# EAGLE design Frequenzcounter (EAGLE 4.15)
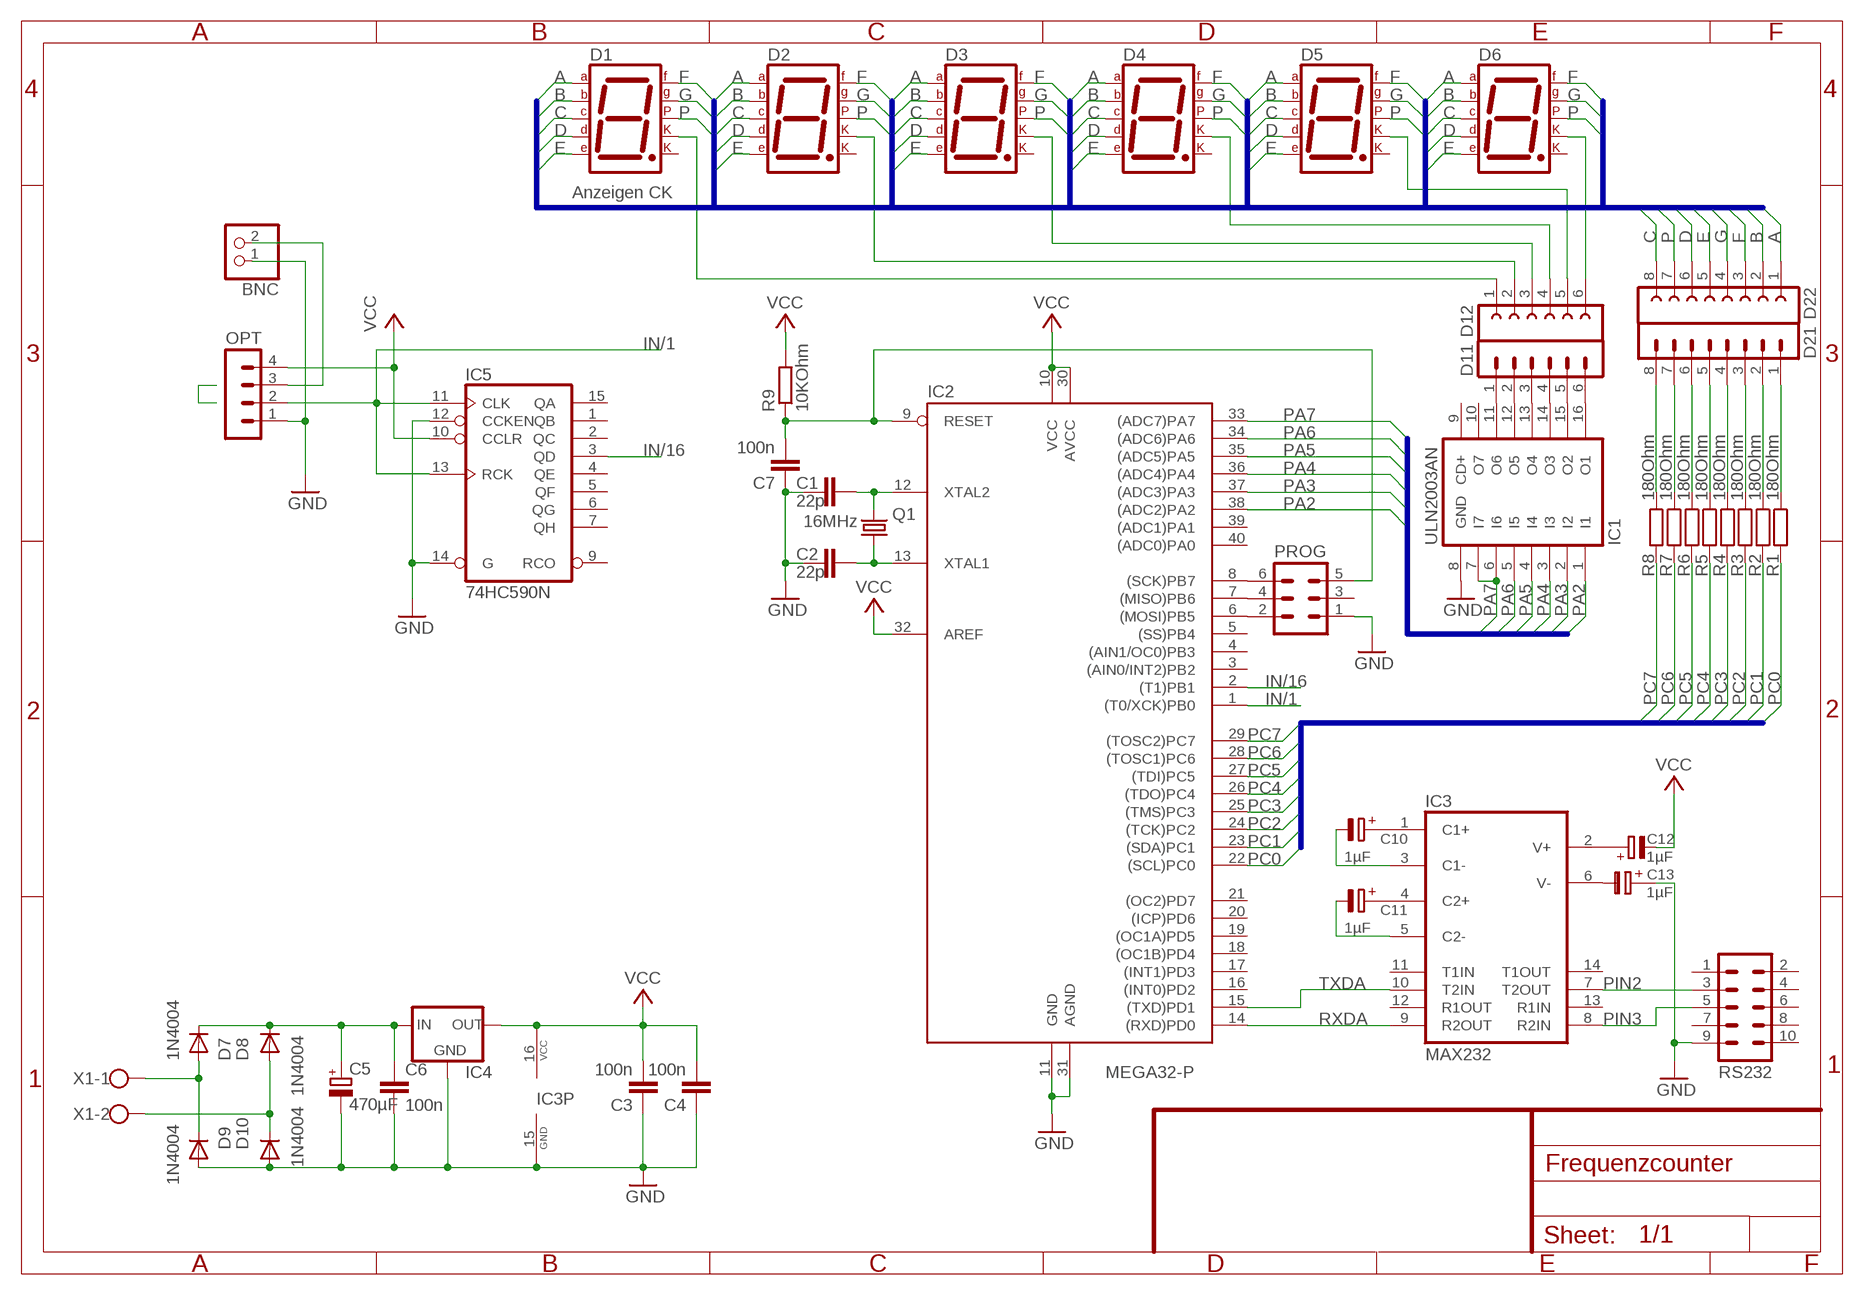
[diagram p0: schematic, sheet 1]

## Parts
BNC  PINHD-1X2  [1X02]
C1  22p  C-EU025-024X044  [C025-024X044]
C2  22p  C-EU025-024X044  [C025-024X044]
C3  100n  C-EU025-024X044  [C025-024X044]
C4  100n  C-EU025-024X044  [C025-024X044]
C5  470µF  CPOL-EUE5-8.5  [E5-8,5]
C6  100n  C-EU025-024X044  [C025-024X044]
C7  100n  C-EU025-024X044  [C025-024X044]
C10  1µF  E2,5-5  [E2,5-5]
C11  1µF  E2,5-5  [E2,5-5]
C12  1µF  E2,5-5  [E2,5-5]
C13  1µF  E2,5-5  [E2,5-5]
D1  7SEG-CK  [7SEG-13]
D2  7SEG-CK  [7SEG-13]
D3  7SEG-CK  [7SEG-13]
D4  7SEG-CK  [7SEG-13]
D5  7SEG-CK  [7SEG-13]
D6  7SEG-CK  [7SEG-13]
D7  1N4004  [DO41-10]
D8  1N4004  [DO41-10]
D9  1N4004  [DO41-10]
D10  1N4004  [DO41-10]
D11  MA06-1  [MA06-1]
D12  FE06-1  [FE06]
D21  MA08-1  [MA08-1]
D22  FE08-1  [FE08]
IC1  ULN2003AN  [DIL16]
IC2  MEGA32-P  [DIL40]
IC3  MAX232  [DIL16]
IC4  78XXS  [78XXS]
IC5  74HC590N  [DIL16]
OPT  MA04-1  [MA04-1]
PROG  ML6  [ML6]
Q1  16MHz  CRYTALHC49S  [HC49/S]
R1  180Ohm  R-EU_0207/10  [0207/10]
R2  180Ohm  R-EU_0207/10  [0207/10]
R3  180Ohm  R-EU_0207/10  [0207/10]
R4  180Ohm  R-EU_0207/10  [0207/10]
R5  180Ohm  R-EU_0207/10  [0207/10]
R6  180Ohm  R-EU_0207/10  [0207/10]
R7  180Ohm  R-EU_0207/10  [0207/10]
R8  180Ohm  R-EU_0207/10  [0207/10]
R9  10KOhm  R-EU_0207/10  [0207/10]
RS232  ML10  [ML10]
X1  W237-102  [W237-102]

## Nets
A: D1.7(A) D2.7(A) D3.7(A) D4.7(A) D5.7(A) D6.7(A) D22.1
B: D1.6(B) D2.6(B) D3.6(B) D4.6(B) D5.6(B) D6.6(B) D22.2
C: D1.4(C) D2.4(C) D3.4(C) D4.4(C) D5.4(C) D6.4(C) D22.8
D: D1.2(D) D2.2(D) D3.2(D) D4.2(D) D5.2(D) D6.2(D) D22.6
E: D1.1(E) D2.1(E) D3.1(E) D4.1(E) D5.1(E) D6.1(E) D22.5
F: D1.9(F) D2.9(F) D3.9(F) D4.9(F) D5.9(F) D6.9(F) D22.3
G: D1.10(G) D2.10(G) D3.10(G) D4.10(G) D5.10(G) D6.10(G) D22.4
GND: BNC.1 C1.1 C2.1 C3.1 C4.1 C5.- C6.2 C7.1 C13.+ D9.A D10.A IC1.8(GND) IC2.11(GND) IC2.31(AGND) IC3.15(GND) IC4.GND IC5.12(CCKEN) IC5.14(G) OPT.1 PROG.1 RS232.9
IN/1: IC2.1((T0/XCK)PB0) IC5.11(CLK) IC5.13(RCK) OPT.2
IN/16: IC2.2((T1)PB1) IC5.3(QD)
N$1: D21.8 R8.1
N$2: D2.3(CK1) D12.2
N$3: D3.3(CK1) D12.3
N$4: D4.3(CK1) D12.4
N$5: D5.3(CK1) D12.5
N$6: D6.3(CK1) D12.6
N$7: D21.7 R7.1
N$8: D21.6 R6.1
N$9: D21.5 R5.1
N$10: D21.4 R4.1
N$11: D21.3 R3.1
N$12: D21.2 R2.1
N$13: D21.1 R1.1
N$14: D11.6 IC1.16(O1)
N$15: D11.5 IC1.15(O2)
N$16: D11.4 IC1.14(O3)
N$17: D11.3 IC1.13(O4)
N$18: D11.2 IC1.12(O5)
N$19: D11.1 IC1.11(O6)
N$20: C10.+ IC3.1(C1+)
N$21: C11.+ IC3.4(C2+)
N$22: C11.- IC3.5(C2-)
N$23: C12.+ IC3.2(V+)
N$24: C13.- IC3.6(V-)
N$27: C1.2 IC2.12(XTAL2) Q1.2
N$28: C2.2 IC2.13(XTAL1) Q1.1
N$30: C10.- IC3.3(C1-)
N$35: IC2.6((MOSI)PB5) PROG.2
N$36: IC2.7((MISO)PB6) PROG.4
N$37: IC2.8((SCK)PB7) PROG.6
N$42: D7.A D9.C X1.1
N$43: D8.A D10.C X1.2
N$44: BNC.2 OPT.3
N$45: C5.+ C6.1 D7.C D8.C IC4.IN
P: D1.5(DP) D2.5(DP) D3.5(DP) D4.5(DP) D5.5(DP) D6.5(DP) D22.7
PA2: IC1.1(I1) IC2.38((ADC2)PA2)
PA3: IC1.2(I2) IC2.37((ADC3)PA3)
PA4: IC1.3(I3) IC2.36((ADC4)PA4)
PA5: IC1.4(I4) IC2.35((ADC5)PA5)
PA6: IC1.5(I5) IC2.34((ADC6)PA6)
PA7: IC1.6(I6) IC1.7(I7) IC2.33((ADC7)PA7)
PC0: IC2.22((SCL)PC0) R1.2
PC1: IC2.23((SDA)PC1) R2.2
PC2: IC2.24((TCK)PC2) R3.2
PC3: IC2.25((TMS)PC3) R4.2
PC4: IC2.26((TDO)PC4) R5.2
PC5: IC2.27((TDI)PC5) R6.2
PC6: IC2.28((TOSC1)PC6) R7.2
PC7: IC2.29((TOSC2)PC7) R8.2
PIN2: IC3.7(T2OUT) RS232.3
PIN3: IC3.8(R2IN) RS232.5
RESET: C7.2 IC2.9(RESET) PROG.5 R9.1
RXDA: IC2.14((RXD)PD0) IC3.9(R2OUT)
SEG1: D1.3(CK1) D12.1
TXDA: IC2.15((TXD)PD1) IC3.10(T2IN)
VCC: C3.2 C4.2 C12.- IC2.10(VCC) IC2.30(AVCC) IC2.32(AREF) IC3.16(VCC) IC4.OUT IC5.10(CCLR) OPT.4 R9.2
Unconnected: D1.8(CK2) D2.8(CK2) D3.8(CK2) D4.8(CK2) D5.8(CK2) D6.8(CK2) IC1.9(CD+) IC1.10(O7) IC2.3((AIN0/INT2)PB2) IC2.4((AIN1/OC0)PB3) IC2.5((SS)PB4) IC2.16((INT0)PD2) IC2.17((INT1)PD3) IC2.18((OC1B)PD4) IC2.19((OC1A)PD5) IC2.20((ICP)PD6) IC2.21((OC2)PD7) IC2.39((ADC1)PA1) IC2.40((ADC0)PA0) IC3.11(T1IN) IC3.12(R1OUT) IC3.13(R1IN) IC3.14(T1OUT) IC5.1(QB) IC5.2(QC) IC5.4(QE) IC5.5(QF) IC5.6(QG) IC5.7(QH) IC5.9(RCO) IC5.15(QA) PROG.3 RS232.1 RS232.2 RS232.4 RS232.6 RS232.7 RS232.8 RS232.10

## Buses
A,B,C,D,E,F,G,P
PC[0..7]
PA[2..7]

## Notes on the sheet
- Anzeigen CK

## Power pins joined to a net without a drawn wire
GND: IC5.8(GND)
VCC: IC5.16(VCC)

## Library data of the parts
BNC = pinhead:PINHD-1X2: PIN HEADER
C1-C4 C6 C7 = rcl:C-EU: CAPACITOR, European symbol
C5 = rcl:CPOL-EU: POLARIZED CAPACITOR, European symbol
C10-C13 = POLCAP:E2,5-5
D1-D6 = special:7SEG-CK: 7-segment DISPLAY single cathode, 13 mm
D7-D10 = diode:1N4004: DIODE
D11 = con-lstb:MA06-1: PIN HEADER
D12 = con-lsta:FE06-1: FEMALE HEADER
D21 = con-lstb:MA08-1: PIN HEADER
D22 = con-lsta:FE08-1: FEMALE HEADER
IC1 = uln-udn:ULN2003A: DRIVER ARRAY
IC2 = atmel:MEGA32-P: MICROCONTROLLER 32 Kbytes FLASH 2 Kbytes SRAM 1 Kbytes EEPROM USART 8-channel 10 bit ADC
IC3 = MAXIM:MAX232
IC4 = v-reg:78XXS: VOLTAGE REGULATOR
IC5 = 74xx-eu:74*590: 8-bit binary COUNTER, output register
OPT = con-lstb:MA04-1: PIN HEADER
PROG = con-harting-ml:ML6: HARTING
Q1 = crystal:CRYTAL: CRYSTAL
R1-R9 = rcl:R-EU_: RESISTOR, European symbol
RS232 = con-harting-ml:ML10: HARTING
X1 = con-wago-500:W237-102: WAGO SCREW CLAMP

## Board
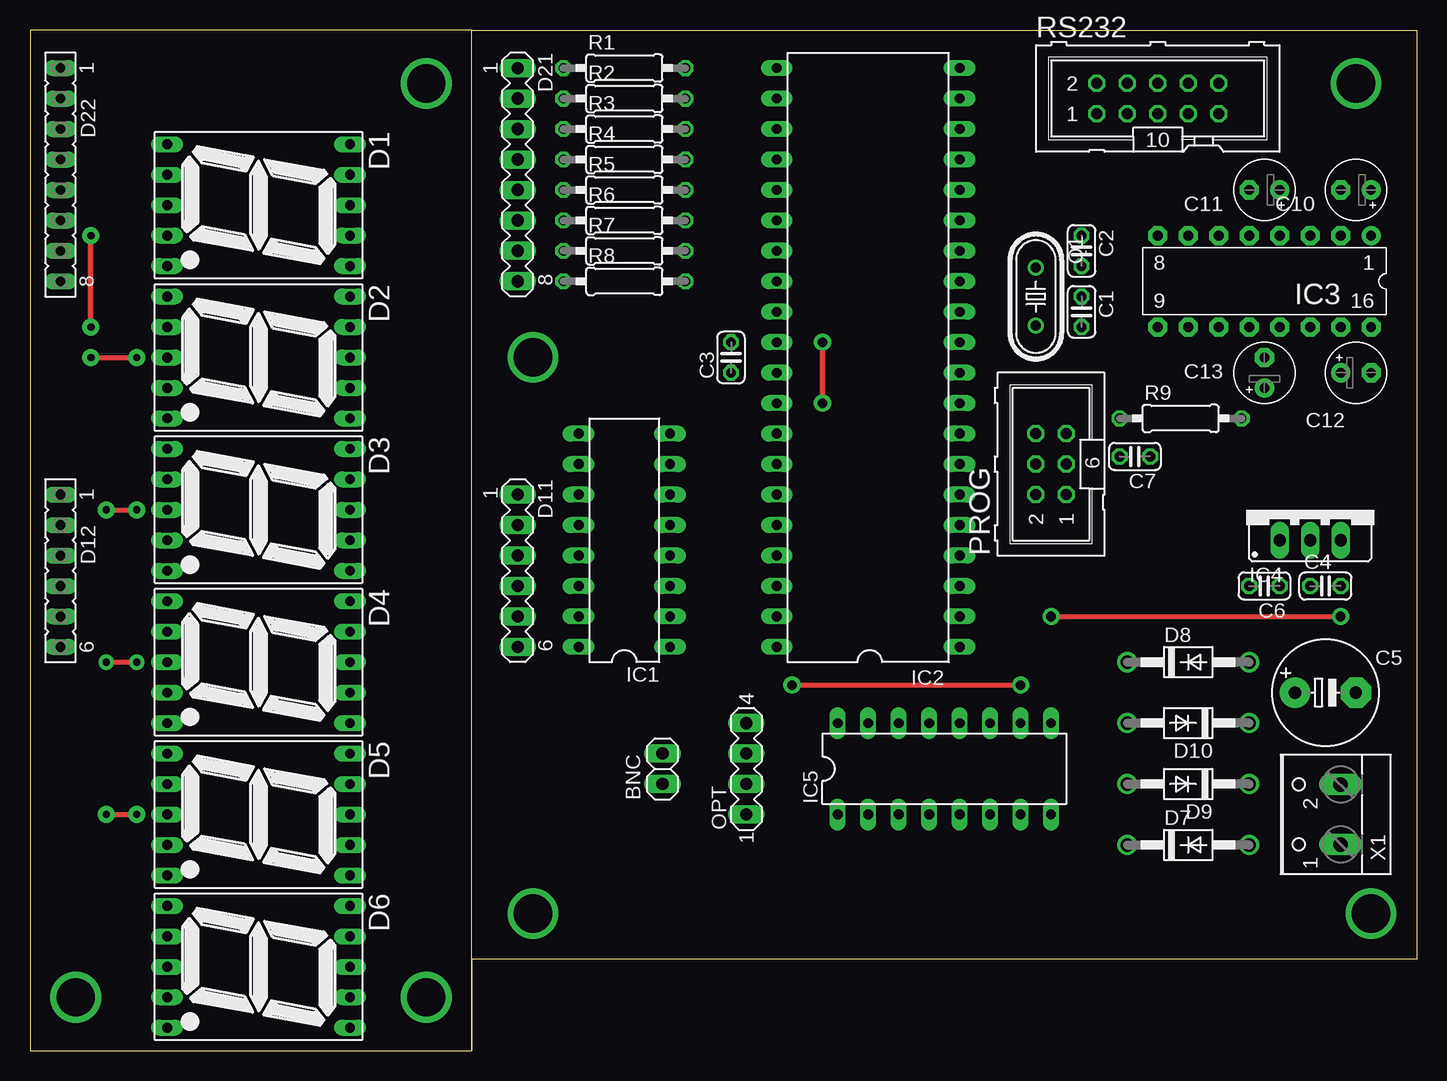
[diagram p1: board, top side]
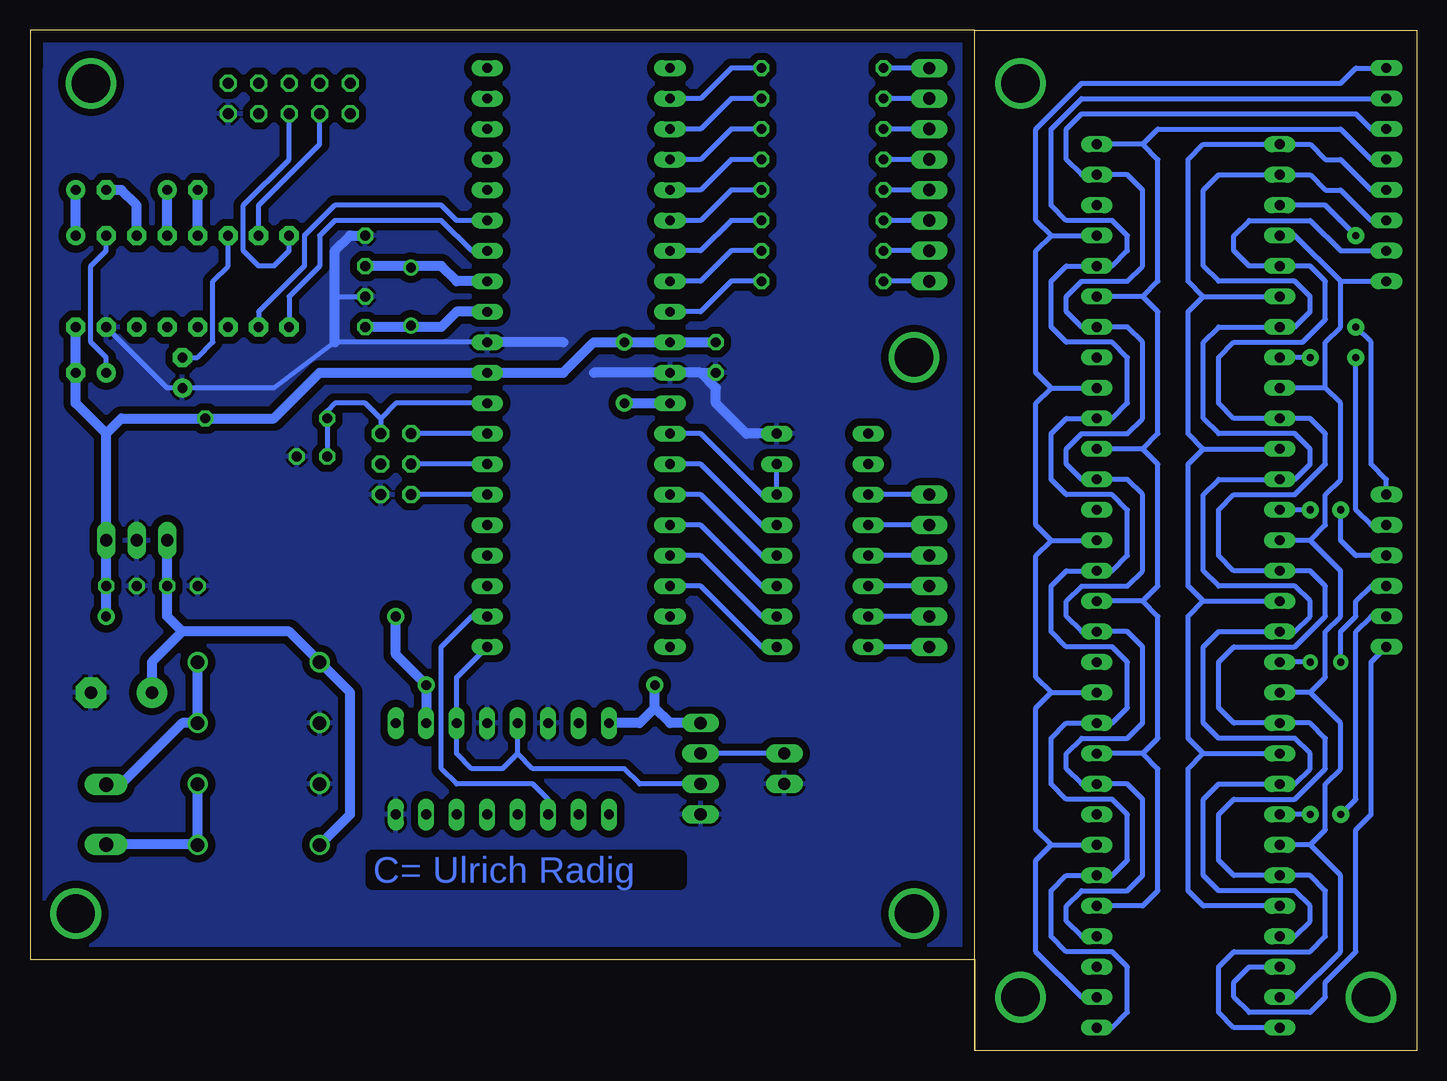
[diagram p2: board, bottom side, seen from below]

Size 115.57 x 85.09 mm. Coordinates in mm from the lower left corner, seen from the top.
Outline: 36.83,0 36.83,85.09
Outline: 36.83,85.09 0,85.09 0,0 36.83,0
Outline: 36.83,85.09 115.57,85.09 115.57,7.62 36.83,7.62 36.83,0
Copper layers (1*16): Top 0.035mm / dielectric 1.5mm / Bottom 0.035mm
Design rules "default": minimum track width 10mil, minimum drill 24mil, track to track 8mil, track to pad 8mil, pad to pad 8mil, via to via 8mil, smd to smd 8mil, copper to edge 40mil, drill to drill 8mil, minimum pad ring 10mil, minimum via ring 8mil, stop-mask expansion 4mil, vias tented up to drill 0mil, thermal gap 10mil

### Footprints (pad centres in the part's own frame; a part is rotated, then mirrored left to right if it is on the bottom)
1X02 = drill 1.016 long: 1 -1.27,0; 2 1.27,0
C025-024X044 = drill 0.813 octagon: 1 -1.27,0; 2 1.27,0
E5-8,5 = drill 1.016 pad 2.54 round: + -2.54,0 | drill 1.016 pad 2.54 octagon: - 2.54,0
E2,5-5 = drill 0.813 pad 1.6 round: + -1.27,0 | drill 0.813 pad 1.6 octagon: - 1.27,0
7SEG-13 = drill 0.813 long: 1 -5.08,-7.62; 2 -2.54,-7.62; 3 0,-7.62; 4 2.54,-7.62; 5 5.08,-7.62; 6 5.08,7.62; 7 2.54,7.62; 8 0,7.62; 9 -2.54,7.62; 10 -5.08,7.62
DO41-10 = drill 1.118 round: A 5.08,0; C -5.08,0
MA06-1 = drill 1.016 long: 1 -6.35,0; 2 -3.81,0; 3 -1.27,0; 4 1.27,0; 5 3.81,0; 6 6.35,0
FE06 = drill 0.813 long: 1 -6.35,0; 2 -3.81,0; 3 -1.27,0; 4 1.27,0; 5 3.81,0; 6 6.35,0
MA08-1 = drill 1.016 long: 1 -8.89,0; 2 -6.35,0; 3 -3.81,0; 4 -1.27,0; 5 1.27,0; 6 3.81,0; 7 6.35,0; 8 8.89,0
FE08 = drill 0.813 long: 1 -8.89,0; 2 -6.35,0; 3 -3.81,0; 4 -1.27,0; 5 1.27,0; 6 3.81,0; 7 6.35,0; 8 8.89,0
DIL16 = drill 0.813 long: 1 -8.89,-3.81; 2 -6.35,-3.81; 3 -3.81,-3.81; 4 -1.27,-3.81; 5 1.27,-3.81; 6 3.81,-3.81; 7 6.35,-3.81; 8 8.89,-3.81; 9 8.89,3.81; 10 6.35,3.81; 11 3.81,3.81; 12 1.27,3.81; 13 -1.27,3.81; 14 -3.81,3.81; 15 -6.35,3.81; 16 -8.89,3.81
DIL40 = drill 0.813 long: 1 -24.13,-7.62; 2 -21.59,-7.62; 3 -19.05,-7.62; 4 -16.51,-7.62; 5 -13.97,-7.62; 6 -11.43,-7.62; 7 -8.89,-7.62; 8 -6.35,-7.62; 9 -3.81,-7.62; 10 -1.27,-7.62; 11 1.27,-7.62; 12 3.81,-7.62; 13 6.35,-7.62; 14 8.89,-7.62; 15 11.43,-7.62; 16 13.97,-7.62; 17 16.51,-7.62; 18 19.05,-7.62; 19 21.59,-7.62; 20 24.13,-7.62; 21 24.13,7.62; 22 21.59,7.62; 23 19.05,7.62; 24 16.51,7.62; 25 13.97,7.62; 26 11.43,7.62; 27 8.89,7.62; 28 6.35,7.62; 29 3.81,7.62; 30 1.27,7.62; 31 -1.27,7.62; 32 -3.81,7.62; 33 -6.35,7.62; 34 -8.89,7.62; 35 -11.43,7.62; 36 -13.97,7.62; 37 -16.51,7.62; 38 -19.05,7.62; 39 -21.59,7.62; 40 -24.13,7.62
DIL16' = drill 0.813 pad 1.6 round: 1 -8.89,-3.81 | drill 0.813 pad 1.6 octagon: 2 -6.35,-3.81; 3 -3.81,-3.81; 4 -1.27,-3.81; 5 1.27,-3.81; 6 3.81,-3.81; 7 6.35,-3.81; 8 8.89,-3.81; 9 8.89,3.81; 10 6.35,3.81; 11 3.81,3.81; 12 1.27,3.81; 13 -1.27,3.81; 14 -3.81,3.81; 15 -6.35,3.81; 16 -8.89,3.81
78XXS = drill 1.016 long: GND 0,-2.54; IN -2.54,-2.54; OUT 2.54,-2.54
MA04-1 = drill 1.016 long: 1 -3.81,0; 2 -1.27,0; 3 1.27,0; 4 3.81,0
ML6 = drill 0.914 octagon: 1 -2.54,-1.27; 2 -2.54,1.27; 3 0,-1.27; 4 0,1.27; 5 2.54,-1.27; 6 2.54,1.27
HC49/S = drill 0.813 round: 1 -2.413,0; 2 2.413,0
0207/10 = drill 0.813 octagon: 1 -5.08,0; 2 5.08,0
ML10 = drill 0.914 octagon: 1 -5.08,-1.27; 2 -5.08,1.27; 3 -2.54,-1.27; 4 -2.54,1.27; 5 0,-1.27; 6 0,1.27; 7 2.54,-1.27; 8 2.54,1.27; 9 5.08,-1.27; 10 5.08,1.27
W237-102 = drill 1.194 long: 1 -2.5,-1.27; 2 2.5,-1.27

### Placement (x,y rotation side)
BNC  52.7,23.5 90 top
C1  87.63,61.59 270 top
C2  87.63,66.67 270 top
C3  58.42,57.78 90 top
C4  107.95,38.73 0 top
C5  107.95,29.85 0 top
C6  102.87,38.73 180 top
C7  92.08,49.53 180 top
C10  110.49,71.75 180 top
C11  102.87,71.75 180 top
C12  110.49,56.52 0 top
C13  102.87,56.52 90 top
D1  19.05,70.48 270 top
D2  19.05,57.78 270 top
D3  19.05,45.08 270 top
D4  19.05,32.39 270 top
D5  19.05,19.68 270 top
D6  19.05,6.98 270 top
D7  96.52,17.14 0 top
D8  96.52,32.39 0 top
D9  96.52,22.22 180 top
D10  96.52,27.3 180 top
D11  40.64,40 270 top
D12  2.54,40 270 top
D21  40.64,73.02 270 top
D22  2.54,73.02 270 top
IC1  49.53,42.55 90 top
IC2  69.85,57.78 90 top
IC3  MAX232  [DIL16']  102.87,64.13 180 top
IC4  106.68,45.08 0 top
IC5  76.2,23.5 0 top
OPT  59.69,23.5 90 top
PROG  85.09,48.89 90 top
Q1  83.82,62.86 270 top
R1  49.53,81.91 0 top
R2  49.53,79.38 0 top
R3  49.53,76.83 0 top
R4  49.53,74.3 0 top
R5  49.53,71.75 0 top
R6  49.53,69.21 0 top
R7  49.53,66.67 0 top
R8  49.53,64.13 0 top
R9  95.89,52.7 0 top
RS232  93.98,79.38 0 top
X1  107.95,19.68 90 top

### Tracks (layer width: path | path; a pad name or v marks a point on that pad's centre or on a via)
A
  Bottom 0.406: 30.48,67.94 D1.7 | 30.48,67.94 31.75,66.67 31.75,56.52 30.48,55.24 | 30.48,55.24 D2.7 | 30.48,55.24 31.75,53.97 31.75,43.81 30.48,42.55 | 30.48,42.55 D3.7 | 30.48,42.55 31.75,41.28 31.75,31.11 30.48,29.85 | 30.48,29.85 D4.7 | 30.48,29.85 31.75,28.57 31.75,18.42 30.48,17.14 | 30.48,17.14 D5.7 | 30.48,17.14 31.75,15.88 31.75,8.25 27.94,4.45 D6.7 | D22.1 5.08,81.91 6.35,80.64 27.94,80.64 31.75,76.83 31.75,69.21 30.48,67.94
B
  Bottom 0.406: D6.6 25.4,1.91 24.13,3.18 24.13,6.98 25.4,8.25 29.21,8.25 30.48,9.52 30.48,13.34 29.21,14.61 D5.6 25.4,14.61 24.13,15.88 24.13,19.68 25.4,20.96 29.21,20.96 30.48,22.22 30.48,26.04 29.21,27.3 D4.6 25.4,27.3 24.13,28.57 24.13,32.39 25.4,33.66 29.21,33.66 30.48,34.92 30.48,38.73 29.21,40 D3.6 25.4,40 24.13,41.28 24.13,45.08 25.4,46.36 29.21,46.36 30.48,47.62 30.48,51.44 29.21,52.7 D2.6 25.4,52.7 24.13,53.97 24.13,57.78 25.4,59.05 29.21,59.05 30.48,60.33 30.48,64.13 29.21,65.41 D1.6 25.4,65.41 24.13,66.67 24.13,67.94 25.4,69.21 29.21,69.21 30.48,70.48 30.48,76.83 27.94,79.38 D22.2
C
  Bottom 0.406: D1.4 10.16,67.94 6.35,64.13 | 6.35,64.13 6.35,60.33 7.62,59.05 7.62,55.24 | 7.62,55.24 D2.4 | 7.62,55.24 6.35,53.97 6.35,47.62 7.62,46.36 7.62,43.81 8.89,42.55 | 8.89,42.55 D3.4 | 8.89,42.55 6.35,40 6.35,36.19 7.62,34.92 7.62,31.11 8.89,29.85 | 8.89,29.85 D4.4 | 8.89,29.85 6.35,27.3 6.35,23.5 7.62,22.22 7.62,18.42 8.89,17.14 | 8.89,17.14 D5.4 | D6.4 10.16,4.45 6.35,8.25 6.35,14.61 8.89,17.14 | 6.35,64.13 D22.8
D
  Bottom 0.406: D6.2 10.16,9.52 8.89,10.79 8.89,12.07 10.16,13.34 16.51,13.34 17.78,14.61 17.78,20.96 16.51,22.22 D5.2 10.16,22.22 8.89,23.5 8.89,24.76 10.16,26.04 16.51,26.04 17.78,27.3 17.78,33.66 16.51,34.92 D4.2 10.16,34.92 8.89,36.19 8.89,37.47 10.16,38.73 16.51,38.73 17.78,40 17.78,46.36 16.51,47.62 D3.2 10.16,47.62 8.89,48.89 8.89,50.16 10.16,51.44 16.51,51.44 17.78,52.7 17.78,59.05 16.51,60.33 D2.2 10.16,60.33 8.89,61.59 8.89,62.86 10.16,64.13 16.51,64.13 17.78,65.41 17.78,71.75 16.51,73.02 D1.2 8.89,73.02 7.62,71.75 6.35,71.75 3.81,69.21 D22.6
E
  Bottom 0.406: 17.78,62.86 19.05,64.13 19.05,74.3 17.78,75.56 D1.1 8.89,75.56 7.62,74.3 6.35,74.3 3.81,71.75 D22.5 | 17.78,62.86 D2.1 | 17.78,62.86 19.05,61.59 19.05,51.44 17.78,50.16 | 17.78,50.16 D3.1 | 17.78,50.16 19.05,48.89 19.05,38.73 17.78,37.47 | 17.78,37.47 D4.1 | 17.78,37.47 19.05,36.19 19.05,26.04 17.78,24.76 | 17.78,24.76 D5.1 | 17.78,24.76 19.05,23.5 19.05,13.34 17.78,12.07 D6.1
F
  Bottom 0.406: D6.9 27.94,9.52 29.21,10.79 29.21,12.07 27.94,13.34 24.13,13.34 22.86,14.61 22.86,20.96 24.13,22.22 D5.9 27.94,22.22 29.21,23.5 29.21,24.76 27.94,26.04 24.13,26.04 22.86,27.3 22.86,33.66 24.13,34.92 D4.9 27.94,34.92 29.21,36.19 29.21,37.47 27.94,38.73 24.13,38.73 22.86,40 22.86,46.36 24.13,47.62 D3.9 27.94,47.62 29.21,48.89 29.21,50.16 27.94,51.44 24.13,51.44 22.86,52.7 22.86,59.05 24.13,60.33 D2.9 27.94,60.33 29.21,61.59 29.21,62.86 27.94,64.13 24.13,64.13 22.86,65.41 22.86,71.75 24.13,73.02 D1.9 27.94,73.02 29.21,74.3 29.21,76.83 27.94,78.1 5.08,78.1 3.81,76.83 D22.3
G
  Bottom 0.406: 22.86,75.56 D1.10 | 22.86,75.56 21.59,74.3 21.59,64.13 22.86,62.86 | 22.86,62.86 D2.10 | 22.86,62.86 21.59,61.59 21.59,51.44 22.86,50.16 | 22.86,50.16 D3.10 | 22.86,50.16 21.59,48.89 21.59,38.73 22.86,37.47 | 22.86,37.47 D4.10 | 22.86,37.47 21.59,36.19 21.59,26.04 22.86,24.76 | 22.86,24.76 D5.10 | 22.86,24.76 21.59,23.5 21.59,13.34 22.86,12.07 D6.10 | D22.4 3.81,74.3 6.35,76.83 21.59,76.83 22.86,75.56
GND
  Bottom 0.406: IC2.11 90.17,59.05 95.25,55.24 C13.+ 104.14,55.24 IC3.15 | 90.17,62.86 C1.1
  Bottom 0.813: 90.17,59.05 90.17,62.86 90.17,66.67 88.9,67.94 C2.1 | IC1.8 55.88,51.44 58.42,53.97 58.42,55.24 59.69,56.52 | 59.69,56.52 IC2.31 68.58,56.52 | 71.12,59.05 IC2.11 | 59.69,56.52 C3.1
  pour Bottom (isolate 0.61): 36.83,84.45 114.3,84.45 114.94,8.25 37.47,8.25
IN/1
  Bottom 0.406: 74.93,24.76 73.66,23.5 66.04,23.5 64.77,22.22 OPT.2 | 74.93,24.76 IC5.13 | 74.93,24.76 76.2,23.5 78.74,23.5 80.01,24.76 IC5.11 80.01,31.11 IC2.1
IN/16
  Bottom 0.406: IC5.3 72.39,20.96 73.66,22.22 80.01,22.22 81.28,23.5 81.28,33.66 78.74,36.19 IC2.2
N$1
  Bottom 0.406: D21.8 R8.1
N$2  (via drill 0.6 pad 1.42)
  Top 0.406: v5.08,57.78 v8.89,57.78
  Bottom 0.406: v8.89,57.78 D2.3 | v5.08,57.78 5.08,45.08 3.81,43.81 D12.2
N$3  (via drill 0.6 pad 1.42)
  Top 0.406: v6.35,45.08 v8.89,45.08
  Bottom 0.406: v8.89,45.08 D3.3 | v6.35,45.08 6.35,42.55 5.08,41.28 D12.3
N$4  (via drill 0.6 pad 1.27)
  Top 0.406: v6.35,32.39 v8.89,32.39
  Bottom 0.406: v8.89,32.39 D4.3 | v6.35,32.39 6.35,34.92 5.08,36.19 5.08,37.47 3.81,38.73 D12.4
N$5  (via drill 0.6 pad 1.42)
  Top 0.406: v6.35,19.68 v8.89,19.68
  Bottom 0.406: D12.5 3.81,36.19 5.08,34.92 5.08,20.96 v6.35,19.68 | v8.89,19.68 D5.3
N$6
  Bottom 0.406: D12.6 3.81,32.39 3.81,19.68 5.08,18.42 5.08,8.25 7.62,5.71 7.62,4.45 8.89,3.18 13.97,3.18 15.24,4.45 15.24,5.71 13.97,6.98 D6.3
N$7
  Bottom 0.406: D21.7 R7.1
N$8
  Bottom 0.406: D21.6 R6.1
N$9
  Bottom 0.406: D21.5 R5.1
N$10
  Bottom 0.406: D21.4 R4.1
N$11
  Bottom 0.406: D21.3 R3.1
N$12
  Bottom 0.406: D21.2 R2.1
N$13
  Bottom 0.406: D21.1 R1.1
N$14
  Bottom 0.406: D11.6 IC1.16
N$15
  Bottom 0.406: D11.5 IC1.15
N$16
  Bottom 0.406: D11.4 IC1.14
N$17
  Bottom 0.406: D11.3 IC1.13
N$18
  Bottom 0.406: D11.2 IC1.12
N$19
  Bottom 0.406: D11.1 IC1.11
N$20
  Bottom 0.813: IC3.1 C10.+
N$21
  Bottom 0.813: IC3.4 C11.+
N$22
  Bottom 0.813: IC3.5 C11.-
N$23
  Bottom 0.406: C12.+ 109.22,57.78 110.49,59.05 110.49,65.41 109.22,66.67 IC3.2
N$24
  Bottom 0.406: IC3.6 99.06,65.41 100.33,64.13 100.33,59.05 101.6,57.78 C13.-
N$25  (via drill 3.2)
  other vias: 41.91,57.78
N$27
  Bottom 0.406: 83.82,60.33 Q1.2 83.69,60.45 83.82,60.33
  Bottom 0.813: IC2.12 80.01,61.59 81.28,60.33 83.82,60.33 C1.2
N$28
  Bottom 0.406: 83.82,65.41 Q1.1 83.69,65.28 83.82,65.41
  Bottom 0.813: IC2.13 80.01,64.13 81.28,65.41 83.82,65.41 C2.2
N$29  (via drill 3.2)
  other vias: 110.49,80.64
N$30
  Bottom 0.813: IC3.3 106.68,70.48 107.95,71.75 C10.-
N$32  (via drill 3.2)
  other vias: 3.81,4.45
N$33  (via drill 3.2)
  other vias: 33.02,80.64
N$34  (via drill 3.2)
  other vias: 33.02,4.45
N$35
  Bottom 0.406: IC2.6 PROG.2
N$36
  Bottom 0.406: IC2.7 PROG.4
N$37
  Bottom 0.406: IC2.8 PROG.6
N$42
  Bottom 0.813: X1.1 101.64,17.18 D7.A D9.C
N$43
  Bottom 0.813: X1.2 109.22,22.22 107.95,22.22 102.87,27.3 D10.C D8.A
N$44
  Bottom 0.406: BNC.2 OPT.3
N$45
  Bottom 0.813: D7.C 88.9,19.68 88.9,29.85 D8.C 93.98,34.92 102.87,34.92 | IC4.IN C6.1 104.14,36.19 102.87,34.92 | 102.87,34.92 105.41,32.39 C5.+
N$46  (via drill 3.2)
  other vias: 111.76,11.43
N$48  (via drill 3.2)
  other vias: 41.91,11.43
P
  Bottom 0.406: D6.5 15.24,1.91 16.51,3.18 16.51,6.98 15.24,8.25 8.89,8.25 7.62,9.52 7.62,13.34 8.89,14.61 D5.5 15.24,14.61 16.51,15.88 16.51,19.68 15.24,20.96 10.16,20.96 7.62,23.5 7.62,26.04 8.89,27.3 D4.5 15.24,27.3 16.51,28.57 16.51,32.39 15.24,33.66 10.16,33.66 7.62,36.19 7.62,38.73 8.89,40 D3.5 15.24,40 16.51,41.28 16.51,45.08 15.24,46.36 10.16,46.36 7.62,48.89 7.62,51.44 8.89,52.7 D2.5 15.24,52.7 16.51,53.97 16.51,57.78 15.24,59.05 9.53,59.05 7.62,60.96 7.62,64.13 8.89,65.41 D1.5 13.97,65.41 15.24,66.67 15.24,67.94 13.97,69.21 8.89,69.21 6.35,66.67 D22.7
PA2
  Bottom 0.406: IC1.1 54.61,33.66 59.69,38.73 IC2.38
PA3
  Bottom 0.406: IC1.2 54.61,36.19 59.69,41.28 IC2.37
PA4
  Bottom 0.406: IC1.3 54.61,38.73 59.69,43.81 IC2.36
PA5
  Bottom 0.406: IC1.4 54.61,41.28 59.69,46.36 IC2.35
PA6
  Bottom 0.406: IC1.5 54.61,43.81 59.69,48.89 IC2.34
PA7
  Bottom 0.406: IC2.33 59.69,51.44 54.61,46.36 IC1.6 IC1.7
PC0
  Bottom 0.406: R1.2 57.15,81.91 59.69,79.38 IC2.22
PC1
  Bottom 0.406: R2.2 57.15,79.38 59.69,76.83 IC2.23
PC2
  Bottom 0.406: R3.2 57.15,76.83 59.69,74.3 IC2.24
PC3
  Bottom 0.406: R4.2 57.15,74.3 59.69,71.75 IC2.25
PC4
  Bottom 0.406: R5.2 57.15,71.75 59.69,69.21 IC2.26
PC5
  Bottom 0.406: R6.2 57.15,69.21 59.69,66.67 IC2.27
PC6
  Bottom 0.406: R7.2 57.15,66.67 59.69,64.13 IC2.28
PC7
  Bottom 0.406: R8.2 57.15,64.13 59.69,61.59 IC2.29
PIN2
  Bottom 0.406: RS232.3 91.44,75.56 96.52,70.48 IC3.7
PIN3
  Bottom 0.406: RS232.5 93.98,74.3 97.79,70.48 97.79,66.67 96.52,65.41 95.25,65.41 93.98,66.67 IC3.8
RESET
  Bottom 0.406: IC2.9 85.09,53.97 86.36,52.7 | 86.36,52.7 PROG.5 | C7.2 R9.1 90.81,53.34 90.17,53.97 87.63,53.97 86.36,52.7
RXDA
  Bottom 0.406: IC2.14 78.74,66.67 81.28,69.21 90.17,69.21 91.44,67.94 91.44,65.41 93.98,62.86 IC3.9
SEG1  (via drill 0.6 pad 1.42)
  Top 0.406: v5.08,60.33 v5.08,67.94
  Bottom 0.406: D12.1 2.54,47.62 3.81,48.89 3.81,59.05 v5.08,60.33 | D1.3 7.62,70.48 v5.08,67.94
TXDA
  Bottom 0.406: IC2.15 80.01,69.21 81.28,70.48 90.17,70.48 92.71,67.94 92.71,65.41 96.52,61.59 IC3.10
VCC  (via drill 0.8 pad 1.42)
  Top 0.406: v63.5,30.48 v82.55,30.48 | v85.09,36.19 v109.22,36.19 | v66.04,59.05 v66.04,53.97
  Bottom 0.406: v109.22,36.19 C4.2
  Bottom 0.813: C3.2 IC2.30 v66.04,59.05 68.58,59.05 71.12,56.52 IC2.10 91.44,56.52 95.25,52.7 R9.2 107.95,52.7 109.22,51.44 | IC3.16 C12.- 111.76,53.97 109.22,51.44 | 109.22,51.44 IC4.OUT C4.2 v109.22,36.19 | OPT.4 62.23,27.3 63.5,28.57 | 63.5,28.57 v63.5,30.48 | IC5.10 v82.55,30.48 85.09,33.02 v85.09,36.19 | IC5.16 64.77,27.3 63.5,28.57 | v66.04,53.97 IC2.32

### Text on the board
Bottom: C= Ulrich Radig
